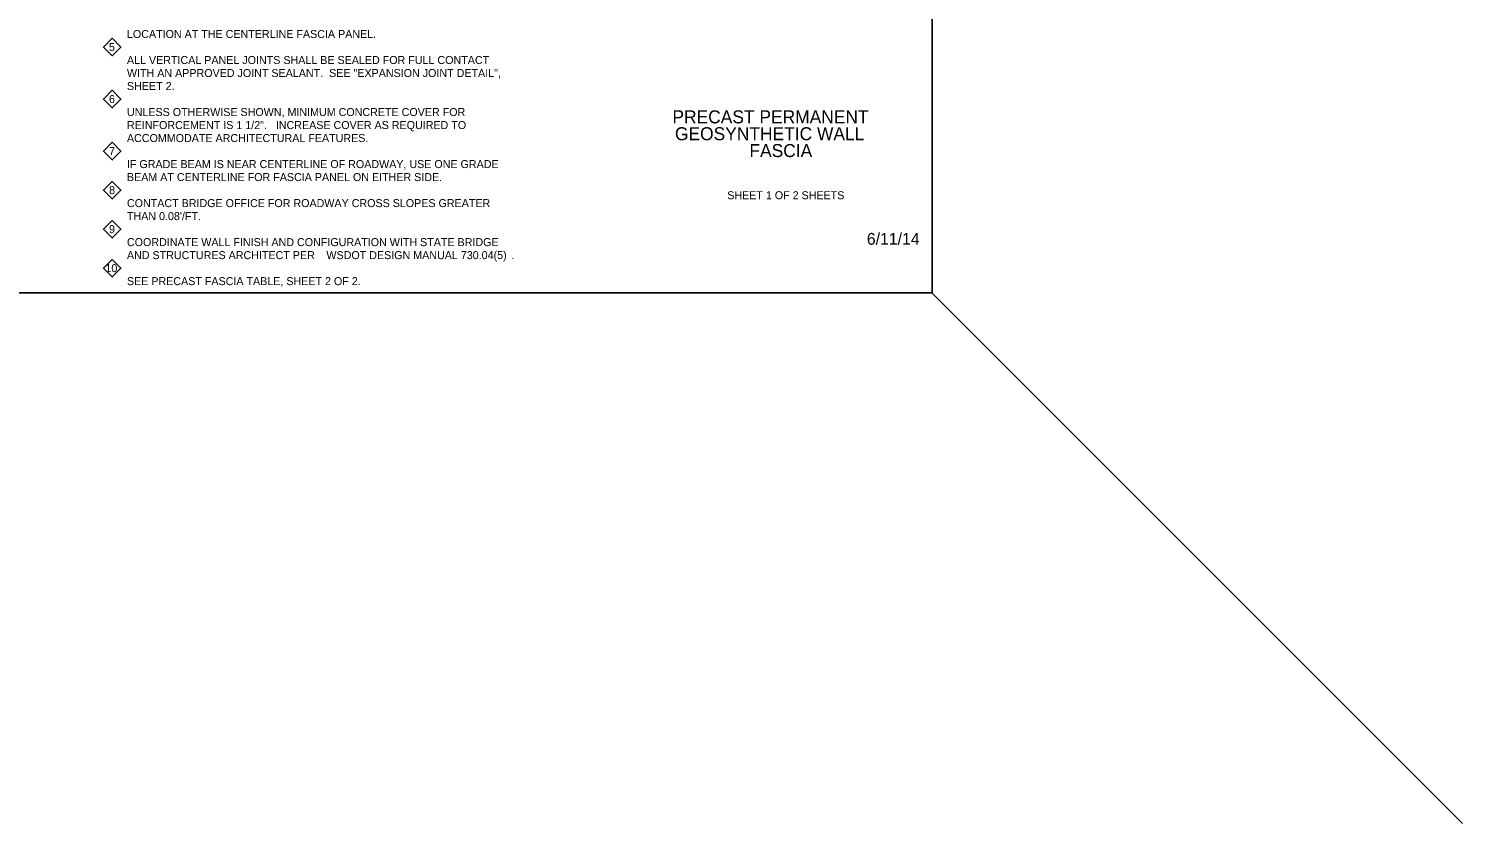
# Model space of a CAD drawing. Extents: x 99862 to 104211, y 98939 to 105076.
# Drawn here: x 101345 to 104211, y 98939 to 100528 of the extents above; entities that cross this region are included whole.
import ezdxf

# ---------------------------------------------------------------- set-up
doc = ezdxf.new("R2010")
doc.units = 0
for name, color, linetype in [('Level 1', 7, 'Continuous'), ('Level 20', 7, 'Continuous'), ('Level 62', 7, 'Continuous')]:
    doc.layers.add(name, color=color, linetype=linetype)

msp = doc.modelspace()

# ---------------------------------------------------------------- linework, layer by layer
at = {"layer": 'Level 1'}
msp.add_line((103150, 100000), (104210.7, 98939.3), dxfattribs=at)
msp.add_lwpolyline([(99862, 99999.5), (103151, 99999.5), (103151, 102075.5), (99862, 102075.5)], close=True, dxfattribs=at)
at = {"layer": 'Level 20'}
for points in [[(101511.6, 100508.6), (101529.1, 100491.1), (101511.6, 100473.5), (101494, 100491.1)], [(101511.6, 100404.6), (101529.1, 100387.1), (101511.6, 100369.5), (101494, 100387.1)], [(101511.6, 100300.6), (101529.1, 100283.1), (101511.6, 100265.5), (101494, 100283.1)], [(101511.6, 100222.6), (101529.1, 100205.1), (101511.6, 100187.5), (101494, 100205.1)], [(101511.6, 100144.6), (101529.1, 100127.1), (101511.6, 100109.5), (101494, 100127.1)], [(101511.6, 100066.6), (101529.1, 100049.1), (101511.6, 100031.5), (101494, 100049.1)]]:
    msp.add_lwpolyline(points, close=True, dxfattribs=at)

# ---------------------------------------------------------------- texts
at = {"layer": 'Level 1'}
msp.add_text('6/11/14', height=23.62, dxfattribs=at).set_placement((103020.3, 100095.8))
at = {"layer": 'Level 20'}
for s, p in [('LOCATION AT THE CENTERLINE FASCIA PANEL.', (101541.1, 100509.1)), ('5', (101505.1, 100483.1)), ('ALL VERTICAL PANEL JOINTS SHALL BE SEALED FOR FULL CONTACT ', (101541.1, 100457.1)), ('WITH AN APPROVED JOINT SEALANT.  SEE "EXPANSION JOINT DETAIL",', (101541.1, 100431.1)), ('SHEET 2.', (101541.1, 100405.1)), ('6', (101505.1, 100379.1)), ('UNLESS OTHERWISE SHOWN, MINIMUM CONCRETE COVER FOR ', (101541.1, 100353.1)), ('REINFORCEMENT IS 1 1/2".   INCREASE COVER AS REQUIRED TO ', (101541.1, 100327.1)), ('ACCOMMODATE ARCHITECTURAL FEATURES.', (101541.1, 100301.1)), ('7', (101505.3, 100275.1)), ('IF GRADE BEAM IS NEAR CENTERLINE OF ROADWAY, USE ONE GRADE ', (101541.1, 100249.1)), ('BEAM AT CENTERLINE FOR FASCIA PANEL ON EITHER SIDE.', (101541.1, 100223.1)), ('8', (101505.4, 100197.1)), ('CONTACT BRIDGE OFFICE FOR ROADWAY CROSS SLOPES GREATER ', (101541.1, 100171.1)), ("THAN 0.08'/FT.", (101541.1, 100145.1)), ('9', (101505.3, 100119.1)), ('AND STRUCTURES ARCHITECT PER ', (101541.1, 100067.1)), ('COORDINATE WALL FINISH AND CONFIGURATION WITH STATE BRIDGE ', (101541.1, 100093.1)), ('WSDOT DESIGN MANUAL 730.04(5)', (101939.9, 100067.1)), ('10', (101498.1, 100041.1)), ('.', (102309.4, 100067.1)), ('SEE PRECAST FASCIA TABLE, SHEET 2 OF 2.                ', (101541.1, 100015.1))]:
    msp.add_text(s, height=16, dxfattribs=at).set_placement(p)
at = {"layer": 'Level 62'}
for s, height, p in [('PRECAST PERMANENT', 26, (102631.6, 100338.5)), ('GEOSYNTHETIC WALL', 26, (102636.6, 100304.8)), ('FASCIA', 26, (102785.5, 100271.1)), ('SHEET 1 OF 2 SHEETS', 16, (102741.1, 100186.8))]:
    msp.add_text(s, height=height, dxfattribs=at).set_placement(p)

doc.saveas('drawing.dxf')
